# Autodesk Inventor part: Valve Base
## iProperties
Created: 2010-02
Part Number: Valve Base
Document SubType Name: Modeling
Designer: jgehrig
Density: 1 g/cm^3
Author: jgehrig
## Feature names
1. Extrusion1
2. Extrusion2
3. Extrusion3
